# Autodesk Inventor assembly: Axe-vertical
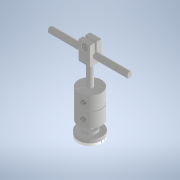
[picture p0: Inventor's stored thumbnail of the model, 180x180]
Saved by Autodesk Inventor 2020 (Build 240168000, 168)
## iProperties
Created: 2023-10
Part Number: Axe-vertical
Document SubType Name: Assembly
Designer: bruno
Author: bruno
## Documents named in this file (8)
- C:\Users\bruno\Documents\1-Cours-2023-24\Maquettes-Inventor\Pince-robot-Dobot\HS422\Axe-vertical.iam
- C:\Users\bruno\Documents\1-Cours-2023-24\Maquettes-Inventor\Pince-robot-Dobot\HS422\Palonier.iam
- C:\Users\bruno\Documents\1-Cours-2023-24\Maquettes-Inventor\Pince-robot-Dobot\Axe-servo.ipt
- C:\Users\bruno\Documents\1-Cours-2023-24\Maquettes-Inventor\Pince-robot-Dobot\Hub.ipt
- C:\Users\bruno\Documents\1-Cours-2023-24\Maquettes-Inventor\Pince-robot-Dobot\Axe-vertical.ipt
- C:\Users\bruno\Documents\1-Cours-2023-24\Maquettes-Inventor\Pince-robot-Dobot\axe-lateral.ipt
- C:\Users\bruno\Documents\Inventor\Content Center Files\R2020\fr-FR\KS B 1003\KS B 1003 - M 3 x 5.ipt
- C:\Users\bruno\Documents\Inventor\Content Center Files\R2020\fr-FR\KS B 1003\KS B 1003 - M 2 x 5.ipt
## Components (8 placed, 7 different names)
1. Palonier:1 [sub-assembly]
2. Axe-servo:1 — Placage:1, Affleurement:1
3. Hub:1 — Placage:1, Affleurement:1, Placage:2, Affleurement:2, Logement:2, Logement:3
4. Axe-vertical:1 — Placage:2, Affleurement:2, Placage:3, Affleurement:3, Logement:1
5. axe-lateral:1 — Placage:3, Affleurement:3
6. KS B 1003 - Métrique M 3 x 5:1 — Logement:1
7. KS B 1003 - Métrique M 2 x 5:1 — Logement:2
8. KS B 1003 - Métrique M 2 x 5:2 — Logement:3
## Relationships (9: Mate 3, Flush 3, Insert 3)
- Placage:1 [Mate]: Axe-servo:1 ↔ Hub:1
- Affleurement:1 [Flush]: Axe-servo:1 ↔ Hub:1
- Placage:2 [Mate]: Hub:1 ↔ Axe-vertical:1
- Affleurement:2 [Flush]: Hub:1 ↔ Axe-vertical:1
- Placage:3 [Mate]: Axe-vertical:1 ↔ axe-lateral:1
- Affleurement:3 [Flush]: Axe-vertical:1 ↔ axe-lateral:1
- Logement:1 [Insert]: Axe-vertical:1 ↔ KS B 1003 - Métrique M 3 x 5:1
- Logement:2 [Insert]: Hub:1 ↔ KS B 1003 - Métrique M 2 x 5:1
- Logement:3 [Insert]: Hub:1 ↔ KS B 1003 - Métrique M 2 x 5:2
